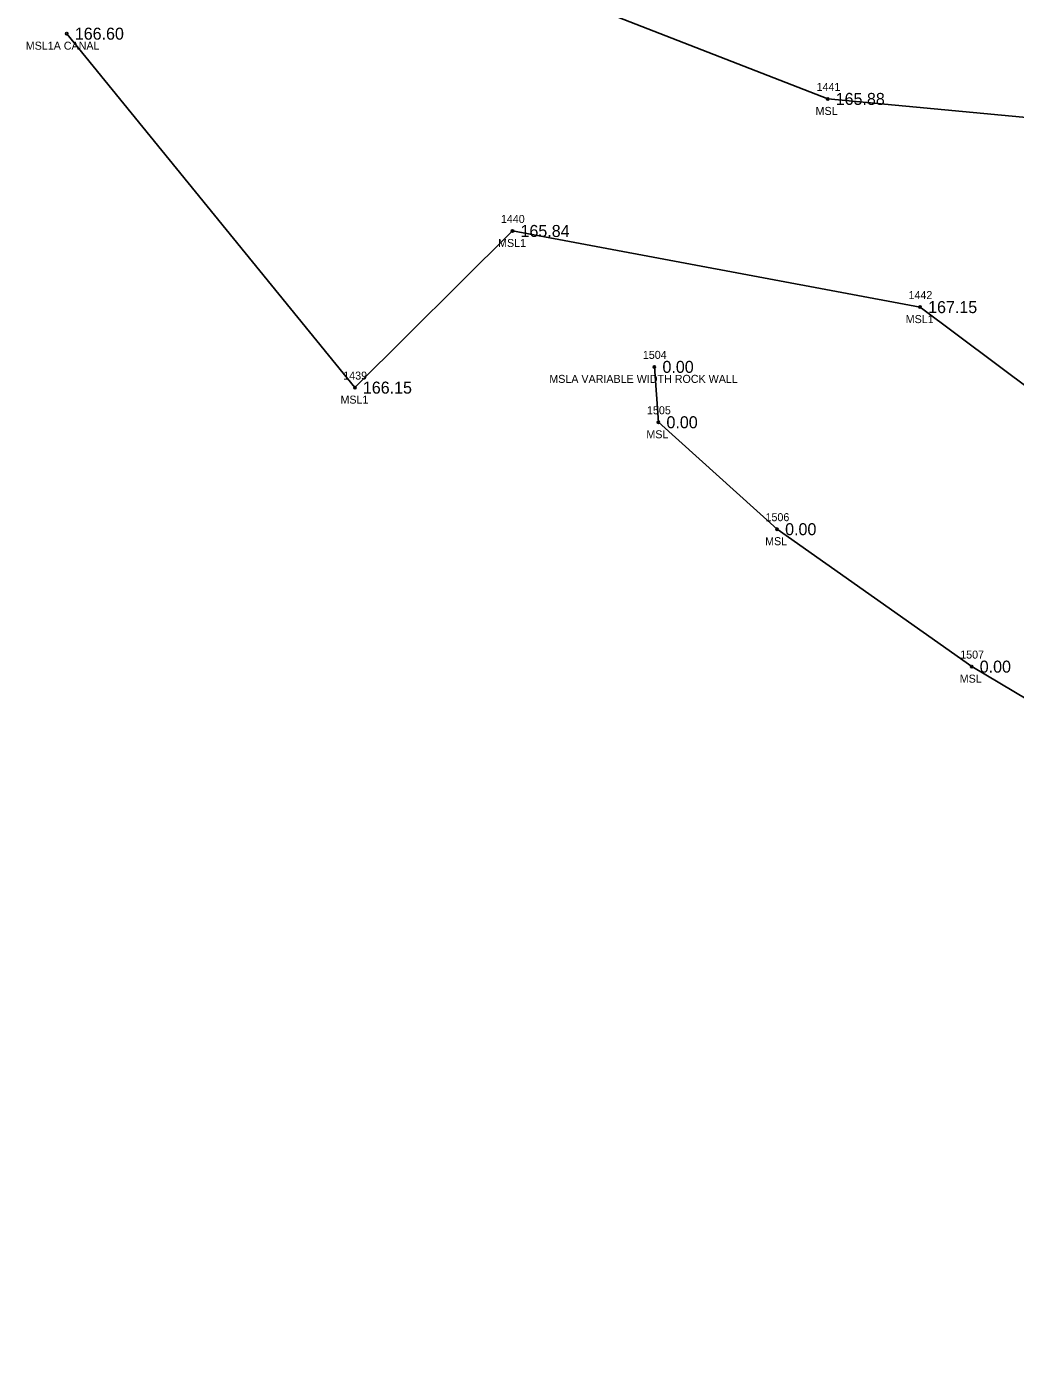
# Model space of a CAD drawing. Extents: x 1969685 to 1970577, y 796315 to 797503.
# Drawn here: x 1969873.6 to 1969997.2, y 796938.5 to 797104.8 of the extents above; entities that cross this region are included whole.
import ezdxf

# ---------------------------------------------------------------- set-up
doc = ezdxf.new("R2010")
doc.units = 0
for name, color, linetype in [('RD_EX_Misc', 7, 'Continuous'), ('RD_EX_Misc_txCode', 7, 'Continuous'), ('RD_EX_TX_Misc_ELEV', 7, 'Continuous'), ('RD_SMD_Locator', 7, 'Continuous')]:
    doc.layers.add(name, color=color, linetype=linetype)

msp = doc.modelspace()

# ---------------------------------------------------------------- linework, layer by layer
at = {"layer": 'RD_EX_Misc'}
for points in [[(1969901.95, 797123.78), (1969973.72, 797095.81), (1970001.64, 797093.18), (1970023.25, 797083.84), (1970037.86, 797069.47), (1970061.54, 797062.66), (1970086.36, 797037.9), (1970106.51, 797017.71), (1970119.68, 797002.07), (1970134.67, 796985.14)], [(1969878.63, 797103.96), (1969914.63, 797059.74), (1969934.33, 797079.31), (1969985.27, 797069.8), (1969999.49, 797059.15), (1970016.11, 797048.45), (1970043.86, 797032.07), (1970068.26, 797003.24), (1970092.92, 796985.07), (1970114.12, 796963.3), (1970132.42, 796938.45)], [(1969952.07, 797062.33), (1969952.57, 797055.41), (1969967.4, 797042.05), (1969991.72, 797024.88), (1970009.25, 797014.48), (1970031.06, 796998.13), (1970050.99, 796982.73), (1970073.18, 796960.02)]]:
    msp.add_lwpolyline(points, dxfattribs=at)
at = {"layer": 'RD_SMD_Locator'}
for centre in [(1969878.63, 797103.96), (1969973.72, 797095.81), (1969934.33, 797079.31), (1969985.27, 797069.8), (1969952.07, 797062.33), (1969914.63, 797059.74), (1969952.57, 797055.41), (1969967.4, 797042.05), (1969991.72, 797024.88)]:
    msp.add_circle(centre, 0.15, dxfattribs=at)

# ---------------------------------------------------------------- texts
at = {"layer": 'RD_EX_Misc_txCode'}
for s, p in [('MSL1A CANAL', (1969873.5, 797101.96)), ('1441', (1969972.33, 797096.81)), ('MSL', (1969972.21, 797093.81)), ('1440', (1969932.88, 797080.31)), ('MSL1', (1969932.53, 797077.31)), ('1442', (1969983.82, 797070.8)), ('MSL1', (1969983.47, 797067.8)), ('1504', (1969950.62, 797063.33)), ('1439', (1969913.18, 797060.74)), ('MSLA VARIABLE WIDTH ROCK WALL', (1969938.93, 797060.33)), ('MSL1', (1969912.83, 797057.74)), ('1505', (1969951.14, 797056.41)), ('MSL', (1969951.06, 797053.41)), ('1506', (1969965.95, 797043.05)), ('MSL', (1969965.9, 797040.05)), ('1507', (1969990.28, 797025.88)), ('MSL', (1969990.22, 797022.88))]:
    msp.add_text(s, height=1, dxfattribs=at).set_placement(p)
at = {"layer": 'RD_EX_TX_Misc_ELEV'}
for s, p in [('166.60', (1969879.63, 797103.21)), ('165.88', (1969974.72, 797095.06)), ('165.84', (1969935.33, 797078.56)), ('167.15', (1969986.27, 797069.05)), ('0.00', (1969953.07, 797061.58)), ('166.15', (1969915.63, 797058.99)), ('0.00', (1969953.57, 797054.66)), ('0.00', (1969968.4, 797041.3)), ('0.00', (1969992.72, 797024.13))]:
    msp.add_text(s, height=1.5, dxfattribs=at).set_placement(p)

doc.saveas('drawing.dxf')
